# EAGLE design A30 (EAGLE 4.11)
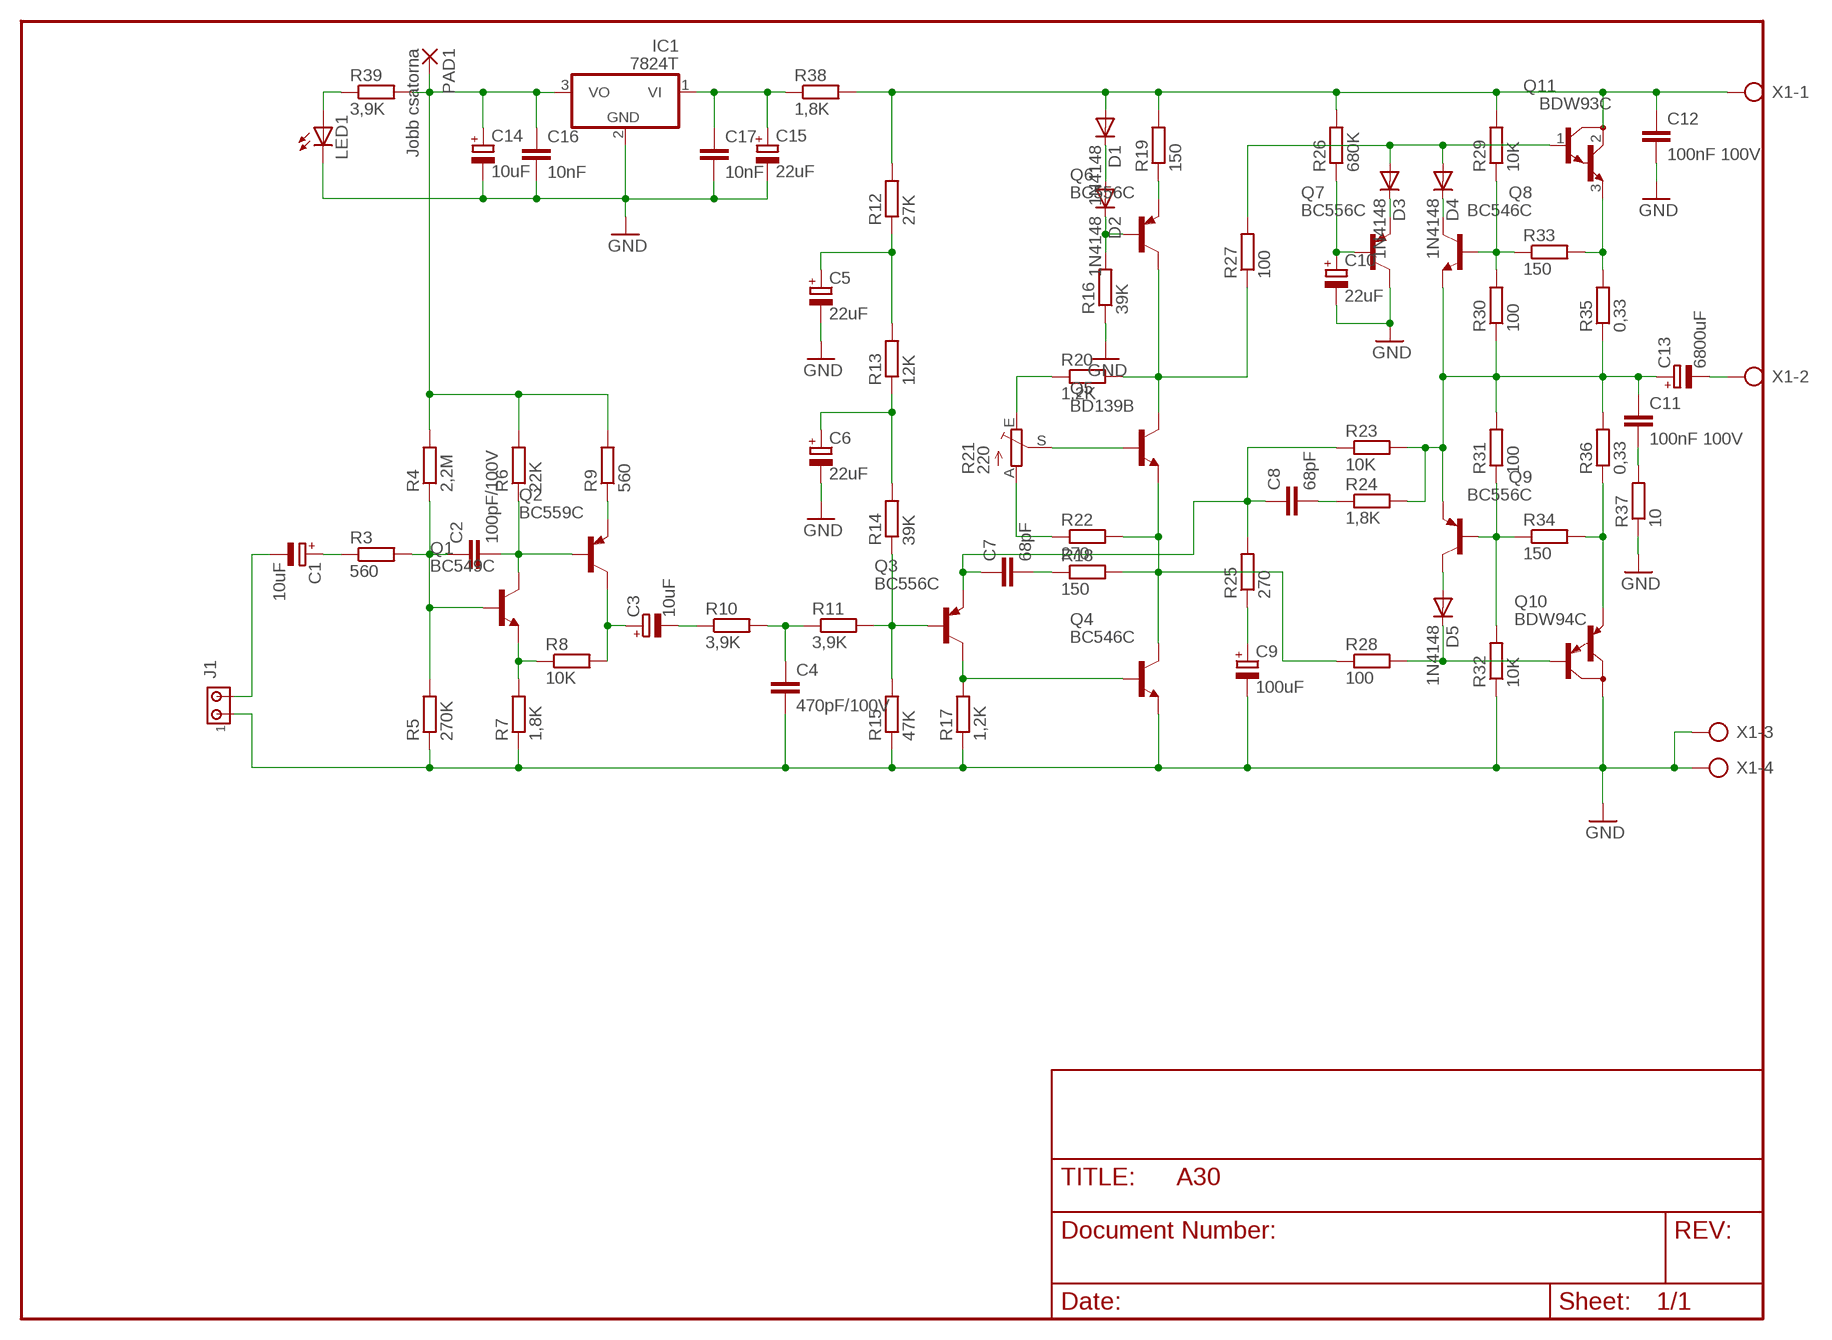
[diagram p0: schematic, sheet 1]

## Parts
C1  10uF  CPOL-EUE5-6  [E5-6]
C2  100pF/100V  C7.5/3  [C7.5B3]
C3  10uF  CPOL-EUE5-6  [E5-6]
C4  470pF/100V  C7.5/3  [C7.5B3]
C5  22uF  CPOL-EUE5-6  [E5-6]
C6  22uF  CPOL-EUE5-6  [E5-6]
C7  68pF  C7.5/3  [C7.5B3]
C8  68pF  C7.5/3  [C7.5B3]
C9  100uF  CPOL-EUE5-6  [E5-6]
C10  22uF  CPOL-EUE5-6  [E5-6]
C11  100nF 100V  C7.5/3  [C7.5B3]
C12  100nF 100V  C7.5/3  [C7.5B3]
C13  6800uF  CPOL-EUE10-22.5  [EB22,5D]
C14  10uF  CPOL-EUE5-6  [E5-6]
C15  22uF  CPOL-EUE5-6  [E5-6]
C16  10nF  C7.5/3  [C7.5B3]
C17  10nF  C7.5/3  [C7.5B3]
D1  1N4148  [DO35-10]
D2  1N4148  [DO35-10]
D3  1N4148  [DO35-10]
D4  1N4148  [DO35-10]
D5  1N4148  [DO35-10]
IC1  7824T  [TO220H]
J1  MTA02-156  [1X2MTA]
LED1  LED5MM  [LED5MM]
PAD1  Jobb csatorna  WIREPAD4,16O1,6  [4,16O1,6]
Q1  BC549C  [TO92-EBC]
Q2  BC559C  [TO92-EBC]
Q3  BC556C  BC556  [TO92-EBC]
Q4  BC546C  BC546A  [TO92-EBC]
Q5  BD139B  BD139  [TO126]
Q6  BC556C  BC556  [TO92-EBC]
Q7  BC556C  BC556  [TO92-EBC]
Q8  BC546C  BC546A  [TO92-EBC]
Q9  BC556C  BC556  [TO92-EBC]
Q10  BDW94C  BDX54  [TO220]
Q11  BDW93C  BDX54  [TO220]
R3  560  R-EU_0207/10  [0207/10]
R4  2,2M  R-EU_0207/10  [0207/10]
R5  270K  R-EU_0207/10  [0207/10]
R6  22K  R-EU_0207/10  [0207/10]
R7  1,8K  R-EU_0207/10  [0207/10]
R8  10K  R-EU_0207/10  [0207/10]
R9  560  R-EU_0207/10  [0207/10]
R10  3,9K  R-EU_0207/10  [0207/10]
R11  3,9K  R-EU_0207/12  [0207/12]
R12  27K  R-EU_0207/10  [0207/10]
R13  12K  R-EU_0207/10  [0207/10]
R14  39K  R-EU_0207/10  [0207/10]
R15  47K  R-EU_0207/10  [0207/10]
R16  39K  R-EU_0207/10  [0207/10]
R17  1,2K  R-EU_0207/10  [0207/10]
R18  150  R-EU_0207/12  [0207/12]
R19  150  R-EU_0207/10  [0207/10]
R20  1,2K  R-EU_0207/10  [0207/10]
R21  220  TRIM_EU-PT10  [PT-10]
R22  270  R-EU_0207/10  [0207/10]
R23  10K  R-EU_0207/10  [0207/10]
R24  1,8K  R-EU_0207/10  [0207/10]
R25  270  R-EU_0207/10  [0207/10]
R26  680K  R-EU_0207/10  [0207/10]
R27  100  R-EU_0207/10  [0207/10]
R28  100  R-EU_0207/10  [0207/10]
R29  10K  R-EU_0207/10  [0207/10]
R30  100  R-EU_0207/10  [0207/10]
R31  100  R-EU_0207/10  [0207/10]
R32  10K  R-EU_0207/10  [0207/10]
R33  150  R-EU_0207/10  [0207/10]
R34  150  R-EU_0207/10  [0207/10]
R35  0,33  R-EU_0411/12  [0411/12]
R36  0,33  R-EU_0411/12  [0411/12]
R37  10  R-EU_0207/10  [0207/10]
R38  1,8K  R-EU_0207/10  [0207/10]
R39  3,9K  R-EU_0207/10  [0207/10]
X1  AK300/4  [AK300/4]

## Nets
GND: C4.2 C5.- C6.- C9.- C10.- C12.2 C14.- C15.- C16.2 C17.2 IC1.2(GND) J1.1 LED1.K(C) Q4.E Q7.C Q10.2(C) R5.1 R7.1 R15.1 R16.1 R17.1 R32.1 R37.1 X1.3 X1.4
N$1: D2.C Q6.B R16.2
N$3: D5.C Q10.1(B) R28.2
N$4: D4.C Q8.C
N$5: D3.C Q7.E
N$6: Q3.B R11.2 R14.1 R15.2
N$7: Q3.C Q4.B R17.2
N$8: Q9.B R31.1 R32.2 R34.1
N$9: C12.1 D1.A Q11.2(C) R12.2 R19.2 R26.2 R29.2 R38.2 X1.1
N$10: D3.A D4.A Q11.1(B) R27.2
N$11: C11.2 R37.2
N$12: C13.- X1.2
N$13: Q8.B R29.1 R30.2 R33.1
N$14: Q11.3(E) R33.2 R35.2
N$15: D5.A Q9.C
N$16: C11.1 C13.+ Q8.E Q9.E R23.2 R24.2 R30.1 R31.2 R35.1 R36.2
N$17: C14.+ C16.1 IC1.3(VO) PAD1.1(P) R4.2 R6.2 R9.2 R39.2
N$18: C8.2 R24.1
N$19: C10.+ Q7.B R26.1
N$20: C9.+ R25.1
N$21: C7.2 R18.1
N$22: C15.+ C17.1 IC1.1(VI) R38.1
N$23: Q6.E R19.1
N$24: C6.+ R13.1 R14.2
N$25: D1.C D2.A
N$26: R20.1 R21.E
N$27: R21.A R22.1
N$28: Q5.3(B) R21.S
N$29: Q4.C Q5.1(E) R18.2 R22.2 R28.1
N$30: Q10.3(E) R34.2 R36.1
N$31: Q5.2(C) Q6.C R20.2 R27.1
N$32: C5.+ R12.1 R13.2
N$33: C3.- R10.1
N$34: C7.1 C8.1 Q3.E R23.1 R25.2
N$35: C2.2 Q1.C Q2.B R6.1
N$36: C4.1 R10.2 R11.1
N$37: Q2.E R9.1
N$38: Q1.E R7.2 R8.1
N$39: C3.+ Q2.C R8.2
N$40: C1.+ R3.1
N$41: C2.1 Q1.B R3.2 R4.1 R5.2
N$42: C1.- J1.2
N$45: LED1.A R39.1

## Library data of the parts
C1 C3 C5 C6 C9 C10 C13-C15 = rcl:CPOL-EU: POLARIZED CAPACITOR, European symbol
C2 C4 C7 C8 C11 C12 C16 C17 = capacitor-wima:C: CAPACITOR
D1-D5 = diode:1N4148: DIODE
IC1 = linear:78*: Positive VOLTAGE REGULATOR
J1 = con-amp:MTA02-156: AMP connector
LED1 = led:LED: LED
PAD1 = wirepad:WIREPAD: Wire PAD connect wire on PCB
Q1 = transistor-npn:BC549*: NPN Transistor
Q2 = transistor-pnp:BC559*: PNP Transistror
Q3 Q6 Q7 Q9 = transistor-pnp:BC556*: PNP Transistror
Q4 Q8 = transistor-npn:BC546*: NPN Transistor
Q5 = transistor-npn:BD139*: NPN Transistor
Q10 = transistor-pnp:BDX54: PNP Darlington Transistor
Q11 = transistor-npn:BDX54*: NPN Darlington Transistor
R3-R20 R22-R39 = rcl:R-EU_: RESISTOR, European symbol
R21 = pot:TRIM_EU-: POTENTIOMETER
X1 = con-ptr500:AK300/4: CONNECTOR

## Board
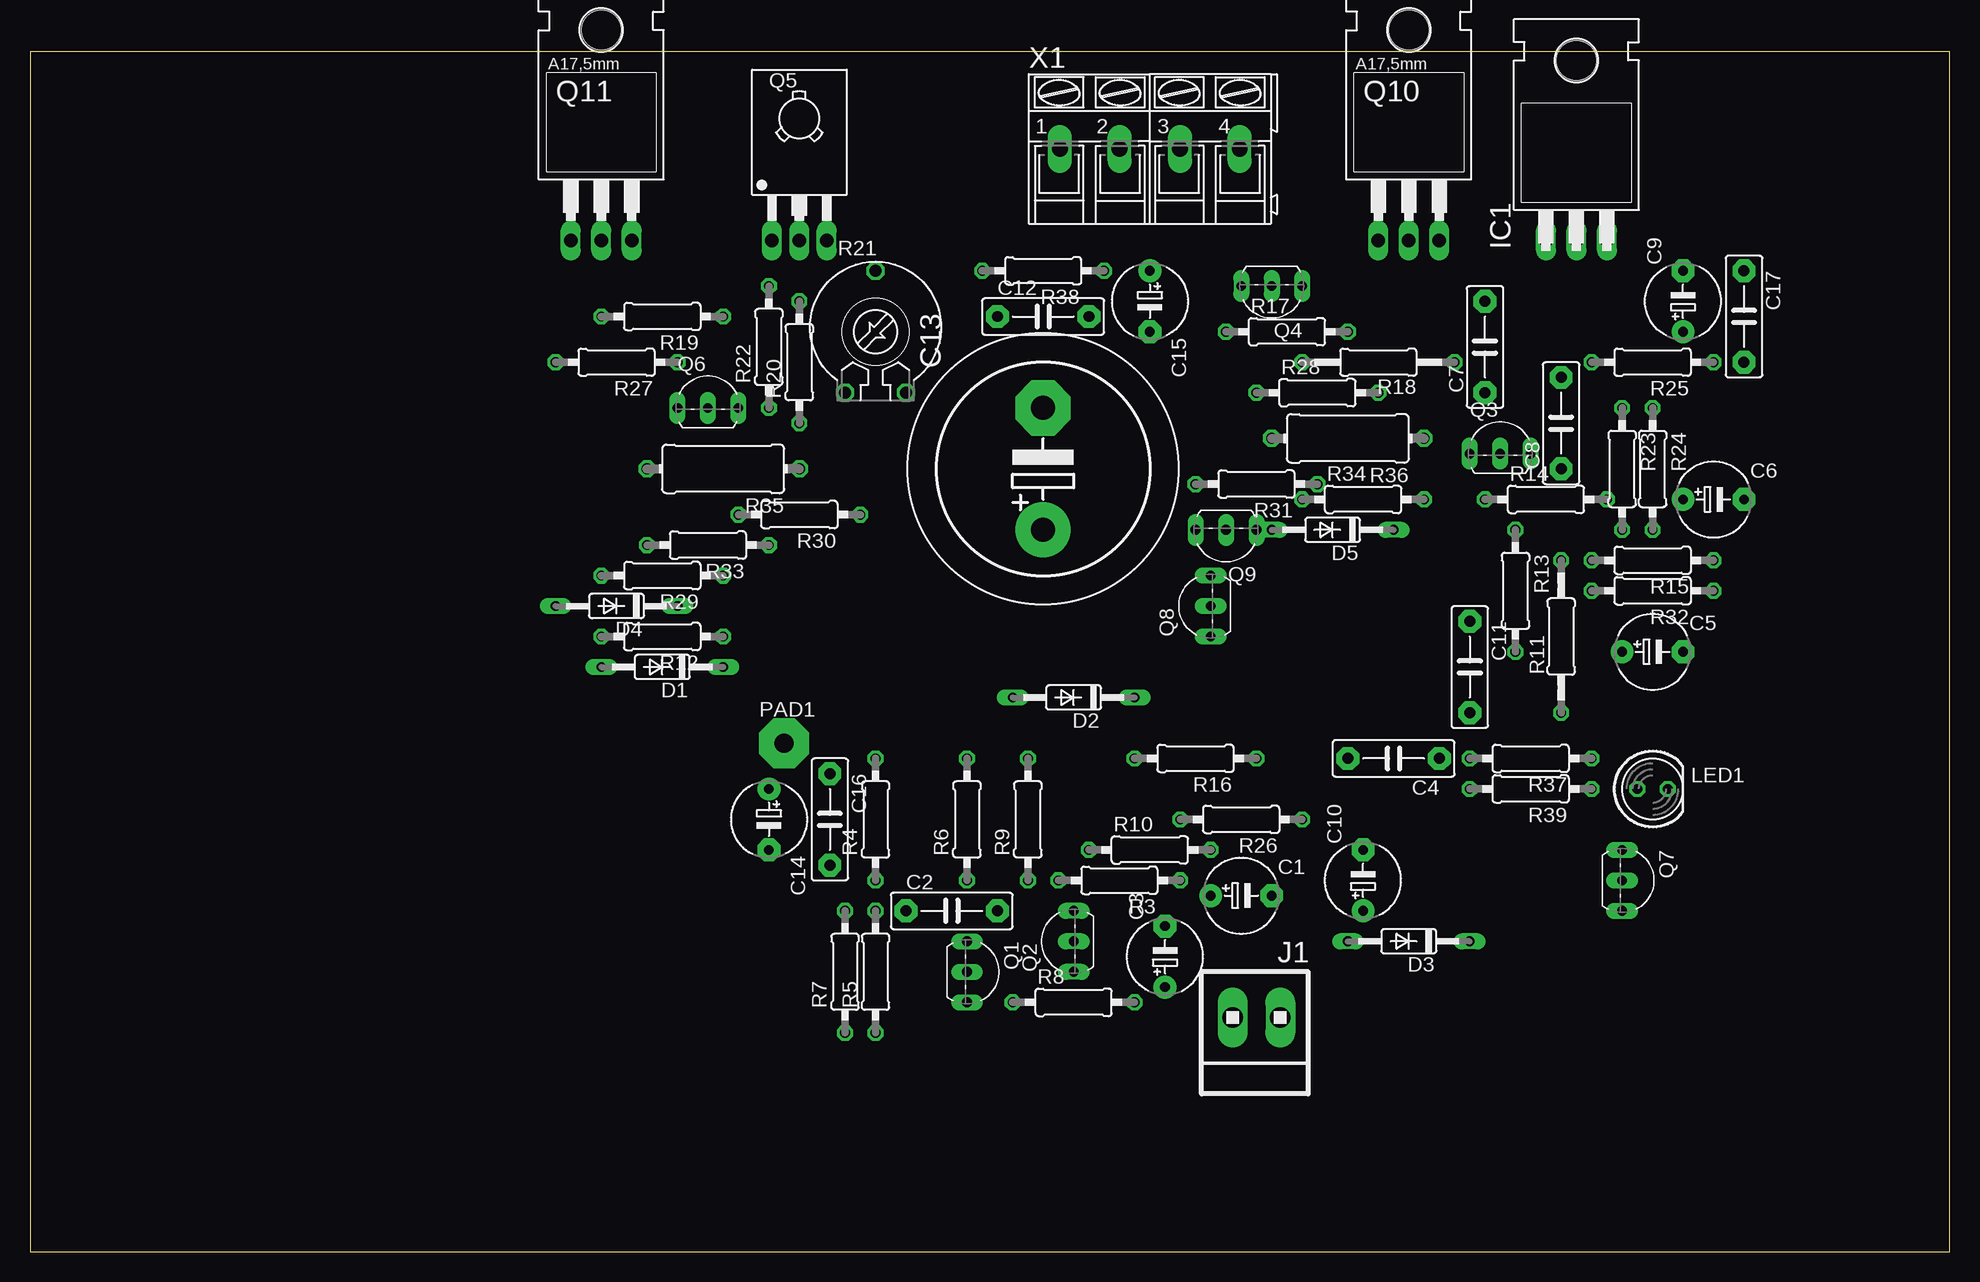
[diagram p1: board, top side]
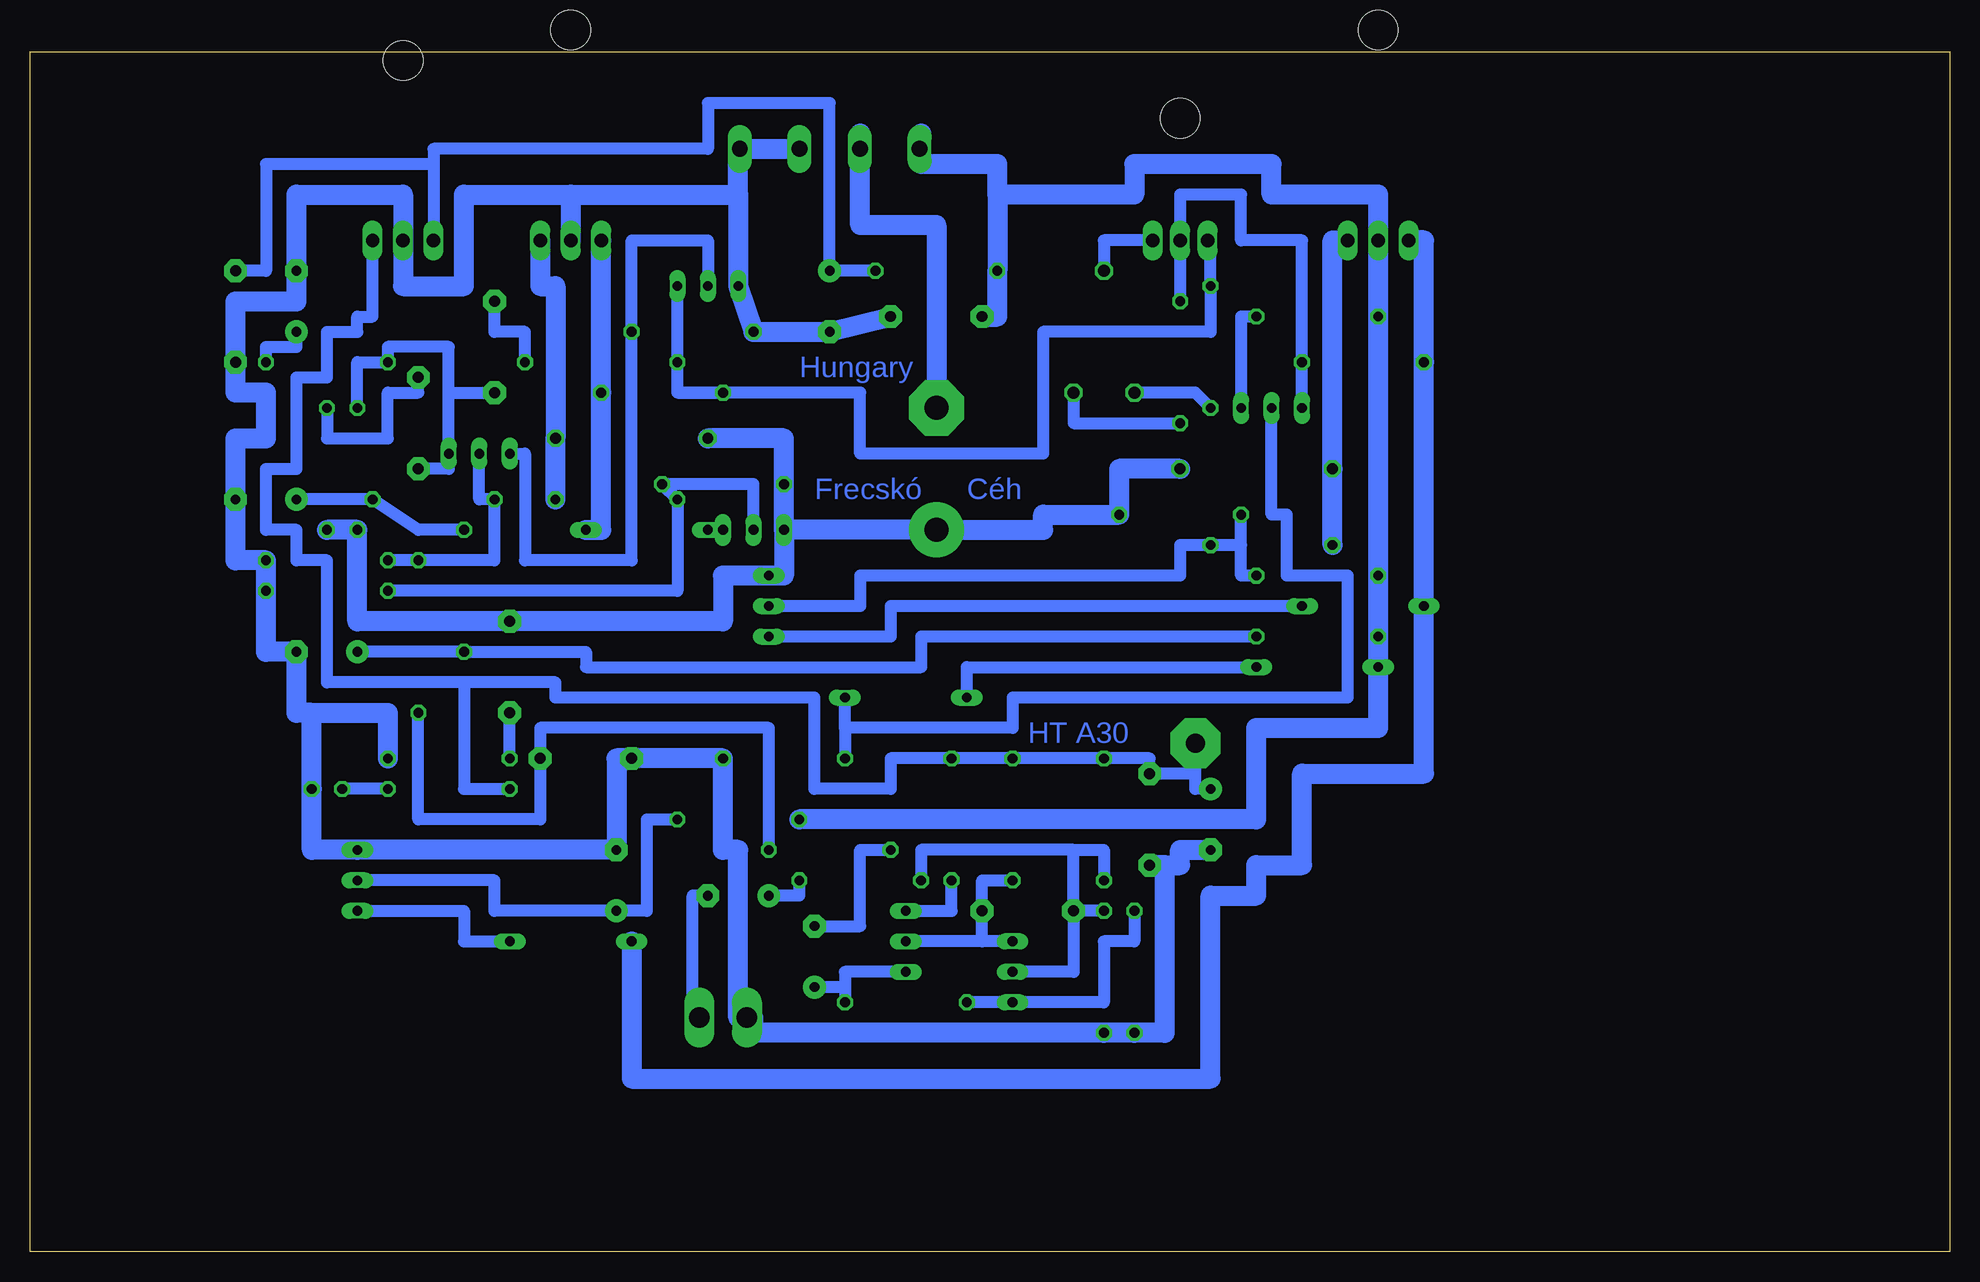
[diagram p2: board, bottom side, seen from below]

Size 160 x 100 mm. Coordinates in mm from the lower left corner, seen from the top.
Outline: 0,0 160,0 160,100 0,100 0,0
Copper layers (1*16): Top 0.035mm / dielectric 1.5mm / Bottom 0.035mm
Design rules "default": minimum track width 10mil, minimum drill 24mil, track to track 8mil, track to pad 8mil, pad to pad 8mil, via to via 8mil, smd to smd 8mil, copper to edge 40mil, drill to drill 8mil, minimum pad ring 10mil, minimum via ring 8mil, stop-mask expansion 4mil, vias tented up to drill 0mil, thermal gap 10mil

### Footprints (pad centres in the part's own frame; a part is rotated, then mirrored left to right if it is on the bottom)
E5-6 = drill 0.813 pad 1.905 round: + -2.54,0 | drill 0.813 pad 1.905 octagon: - 2.54,0
C7.5B3 = drill 0.914 pad 1.905 octagon: 1 -3.81,0; 2 3.81,0
EB22,5D = drill 2.007 pad 4.597 round: + -5.08,0 | drill 2.007 pad 4.597 octagon: - 5.08,0
DO35-10 = drill 0.813 long: A 5.08,0; C -5.08,0
TO220H = drill 1.118 long: 1 -2.54,-10.16; 2 0,-10.16; 3 2.54,-10.16 | hole 3.302: 0,4.826
1X2MTA = drill 1.676 long: 1 1.981,0; 2 -1.981,0
LED5MM = drill 0.813 octagon: A -1.27,0; K 1.27,0
4,16O1,6 = drill 1.6 pad 4.166 octagon: 1 0,0
TO92-EBC = drill 0.813 long: B 0,-1.27; C -2.54,-1.27; E 2.54,-1.27
TO126 = drill 1.118 long: 1 -2.286,-5.08; 2 0,-5.08; 3 2.286,-5.08 | hole 3.302: 0,5.08
TO220 = drill 1.118 long: 1 -2.54,-6.35; 2 0,-6.35; 3 2.54,-6.35 | hole 3.302: 0,11.176
0207/10 = drill 0.813 octagon: 1 -5.08,0; 2 5.08,0
0207/12 = drill 0.813 octagon: 1 -6.35,0; 2 6.35,0
PT-10 = drill 1.016 octagon: A -2.54,-5.08; E 2.54,-5.08; S 0,5.08
0411/12 = drill 0.914 octagon: 1 -6.35,0; 2 6.35,0
AK300/4 = drill 1.321 long: 1 -7.493,0; 2 -2.515,0; 3 2.515,0; 4 7.493,0

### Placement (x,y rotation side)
C1  100.96,29.68 0 top
C2  76.83,28.41 0 top
C3  94.61,24.6 90 top
C4  113.66,41.11 180 top
C5  135.25,50 0 top
C6  140.33,62.7 0 top
C7  121.28,75.4 90 top
C8  127.63,69.05 90 top
C9  137.79,79.21 90 top
C10  111.12,30.95 90 top
C11  120.01,48.73 270 top
C12  84.45,77.94 0 top
C13  84.45,65.24 90 top
C14  61.59,36.03 270 top
C15  93.34,79.21 270 top
C16  66.67,36.03 270 top
C17  142.87,77.94 270 top
D1  52.7,48.73 180 top
D2  86.99,46.19 180 top
D3  114.93,25.87 180 top
D4  48.89,53.81 180 top
D5  108.58,60.16 180 top
IC1  128.9,94.45 0 top
J1  102.23,19.52 180 top
LED1  135.25,38.57 0 top
PAD1  62.86,42.38 0 top
Q1  79.37,23.33 270 top
Q2  85.72,25.87 90 top
Q3  122.55,67.78 0 top
Q4  103.5,79.21 180 top
Q5  64.13,89.37 0 top
Q6  56.51,71.59 0 top
Q7  133.98,30.95 270 top
Q8  97.15,53.81 90 top
Q9  99.69,58.89 180 top
Q10  114.93,90.64 0 top
Q11  47.62,90.64 0 top
R3  90.8,30.95 180 top
R4  70.48,36.03 90 top
R5  70.48,23.33 90 top
R6  78.1,36.03 90 top
R7  67.94,23.33 90 top
R8  86.99,20.79 0 top
R9  83.18,36.03 90 top
R10  93.34,33.49 0 top
R11  127.63,51.27 90 top
R12  52.7,51.27 180 top
R13  123.82,55.08 270 top
R14  126.36,62.7 0 top
R15  135.25,57.62 180 top
R16  97.15,41.11 180 top
R17  104.77,76.67 0 top
R18  112.39,74.13 180 top
R19  52.7,77.94 180 top
R20  64.13,74.13 90 top
R21  70.48,76.67 0 top
R22  61.59,75.4 90 top
R23  132.71,65.24 270 top
R24  135.25,65.24 270 top
R25  135.25,74.13 180 top
R26  100.96,36.03 180 top
R27  48.89,74.13 180 top
R28  107.31,71.59 0 top
R29  52.7,56.35 180 top
R30  64.13,61.43 180 top
R31  102.23,63.97 180 top
R32  135.25,55.08 180 top
R33  56.51,58.89 180 top
R34  111.12,62.7 0 top
R35  57.78,65.24 180 top
R36  109.85,67.78 180 top
R37  125.09,41.11 180 top
R38  84.45,81.75 180 top
R39  125.09,38.57 180 top
X1  93.34,91.91 0 top

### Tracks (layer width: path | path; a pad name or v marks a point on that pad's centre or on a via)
GND
  Bottom 1.676: 114.93,88.1 Q10.2 | 114.93,88.1 100.96,88.1 | 100.96,88.1 100.96,91.91 X1.4 X1.3 | 136.52,44.92 137.79,44.92 C5.- 140.33,50 R32.1 R15.1 142.87,57.62 C6.- 142.87,67.78 140.33,67.78 140.33,71.59 142.87,71.59 C17.2 142.87,79.21 137.79,79.21 C9.- 137.79,88.1 128.9,88.1 IC1.2 128.9,80.48 123.82,80.48 123.82,88.1 114.93,88.1 | 136.52,44.92 130.17,44.92 R37.1 | 136.52,44.92 LED1.K 136.52,33.49 Q7.C C10.- 111.12,41.11 C4.2 R16.1 102.23,33.49 100.96,33.49 100.96,19.52 J1.1 99.69,19.52 99.69,18.25 R5.1 R7.1 65.4,18.25 65.4,32.22 | 100.96,88.1 Q4.E R17.1 C15.- C12.2 | 65.4,32.22 C16.2 | C14.- 64.13,33.49 64.13,32.22 65.4,32.22
N$1
  Bottom 1.016: Q6.B 56.51,61.43 55.24,61.43 55.24,56.35 50.16,56.35 50.16,46.19 78.1,46.19 78.1,43.65 92.07,43.65 | 92.07,43.65 R16.2 | 92.07,43.65 D2.C
N$3
  Bottom 1.676: Q10.1 R28.2 112.39,60.16 D5.C
N$4
  Bottom 1.016: D4.C 88.26,53.81 88.26,51.27 Q8.C
N$5
  Bottom 1.016: Q7.E 123.82,28.41 123.82,25.87 D3.C
N$6
  Bottom 1.016: R15.2 R11.2 121.28,57.62 R14.1 122.55,62.7 Q3.B
N$7
  Bottom 1.016: Q4.B 103.5,84.29 109.85,84.29 R17.2 109.85,57.62 118.74,57.62 118.74,66.51 Q3.C
N$8
  Bottom 1.016: Q9.B 99.69,63.97 R31.1 R34.1 106.04,55.08 R32.2
N$9
  Bottom 1.676: X1.1 85.72,93.18 85.72,90.64 79.37,90.64 79.37,88.1 | R26.2 57.78,36.03 57.78,43.65 47.62,43.65 D1.A R12.2 R29.2 R19.2 Q11.2 47.62,88.1 56.51,88.1 56.51,90.64 67.94,90.64 67.94,88.1 79.37,88.1 | 79.37,88.1 R38.2 79.37,77.94 C12.1
N$10
  Bottom 1.676: Q11.1 43.81,84.29 R27.2 D4.A 43.81,39.84 53.97,39.84 53.97,32.22 57.78,32.22 57.78,29.68 61.59,29.68 61.59,14.44 109.85,14.44 D3.A
N$11
  Bottom 1.016: R37.2 C11.2
N$12
  Bottom 1.676: X1.2 90.8,93.18 90.8,85.56 84.45,85.56 C13.-
N$13
  Bottom 1.016: R29.1 59.05,56.35 59.05,58.89 | 59.05,58.89 R30.2 | 59.05,58.89 R33.1 64.13,58.89 64.13,56.35 90.8,56.35 90.8,53.81 Q8.B
N$14
  Bottom 1.676: Q11.3 51.43,84.29 R35.2 R33.2
N$15
  Bottom 1.016: D5.A Q9.C
N$16
  Bottom 1.676: R35.1 69.21,65.24 R30.1 75.56,61.43 75.56,60.16 C13.+ Q9.E | R36.2 97.15,67.78 R31.2 Q9.E | R24.2 R23.2 132.71,52.54 C11.1 102.23,52.54 102.23,56.35 Q8.E 97.15,56.35 Q9.E
N$17
  Bottom 1.016: 123.82,47.46 135.25,47.46 135.25,57.62 137.79,57.62 137.79,60.16 140.33,60.16 140.33,65.24 137.79,65.24 137.79,72.86 135.25,72.86 135.25,76.67 132.71,76.67 132.71,77.94 131.44,77.94 IC1.3 | R39.2 123.82,38.57 123.82,47.46 | 123.82,47.46 116.2,47.46 116.2,46.19 94.61,46.19 94.61,38.57 88.26,38.57 88.26,41.11 R9.2 R6.2 R4.2 66.67,41.11 C16.1 62.86,39.84 | C14.+ 62.86,38.57 62.86,39.84 | 62.86,39.84 PAD1.1
N$18
  Bottom 1.016: R24.1 135.25,67.78 130.17,67.78 130.17,71.59 127.63,71.59 C8.2
N$19
  Bottom 1.016: R26.1 108.58,36.03 108.58,28.41 C10.+ 121.28,28.41 121.28,30.95 Q7.B
N$20
  Bottom 1.016: R25.1 140.33,75.4 137.79,75.4 C9.+
N$21
  Bottom 1.016: R18.1 118.74,76.67 121.28,76.67 C7.2
N$22
  Bottom 1.016: 126.36,90.64 126.36,91.91 103.5,91.91 103.5,95.72 93.34,95.72 C15.+ R38.1 | 126.36,90.64 IC1.1 | 126.36,90.64 140.33,90.64 140.33,81.75 C17.1
N$23
  Bottom 1.016: R19.1 59.05,77.94 Q6.E
N$24
  Bottom 1.016: C6.+ R14.2 127.63,60.16 R13.1
N$25
  Bottom 1.016: D2.A 81.91,48.73 D1.C
N$26
  Bottom 1.016: R21.E 73.02,69.05 R20.1
N$27
  Bottom 1.016: R21.A 62.86,71.59 R22.1
N$28
  Bottom 1.016: Q5.3 70.48,84.29 R21.S
N$29
  Bottom 1.016: 106.04,71.59 R28.1 | 106.04,71.59 R18.2 Q4.C | 106.04,71.59 90.8,71.59 90.8,66.51 75.56,66.51 75.56,76.67 61.59,76.67 R22.2 61.59,84.29 Q5.1
N$30
  Bottom 1.676: R34.2 R36.1 116.2,80.48 117.47,80.48 Q10.3
N$31
  Bottom 1.016: Q6.C R27.1 53.97,84.29 59.05,84.29 59.05,88.1 64.13,88.1 Q5.2 R20.2
N$32
  Bottom 1.016: C5.+ R13.2 113.66,50 113.66,48.73 85.72,48.73 85.72,51.27 R12.1
N$33
  Bottom 1.016: C3.- 90.8,27.14 90.8,33.49 R10.1
N$34
  Bottom 1.016: 125.09,71.59 C7.1 | 125.09,71.59 Q3.E 125.09,65.24 C8.1 | 125.09,71.59 125.09,75.4 130.17,75.4 R25.2 132.71,74.13 R23.1
N$35
  Bottom 1.016: Q1.C 80.64,25.87 | 80.64,25.87 Q2.B | R6.1 80.64,30.95 C2.2 80.64,25.87
N$36
  Bottom 1.016: R11.1 127.63,36.03 117.47,36.03 C4.1 117.47,43.65 98.42,43.65 R10.2
N$37
  Bottom 1.016: Q2.E 83.18,28.41 R9.1
N$38
  Bottom 1.016: R8.1 Q1.E 70.48,20.79 70.48,25.87 67.94,25.87 R7.2
N$39
  Bottom 1.016: 92.07,22.06 R8.2 | 92.07,22.06 C3.+ | Q2.C 92.07,23.33 92.07,22.06
N$40
  Bottom 1.016: R3.1 95.88,29.68 C1.+
N$41
  Bottom 1.016: R3.2 85.72,33.49 73.02,33.49 | 73.02,33.49 70.48,33.49 R4.1 | Q1.B 73.02,23.33 C2.1 | R5.2 C2.1 | C2.1 73.02,33.49
N$42
  Bottom 1.016: C1.- 104.77,29.68 104.77,18.25 J1.2
N$45
  Bottom 1.016: R39.1 LED1.A

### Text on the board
Bottom: Hungary | Céh | Frecskó | HT A30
